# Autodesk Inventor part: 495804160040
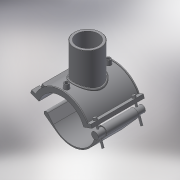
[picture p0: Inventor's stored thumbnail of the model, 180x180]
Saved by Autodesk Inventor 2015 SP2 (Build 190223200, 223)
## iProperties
Created: 2017-07
Part Number: 495804160040
Material: Generic
Description: PLASSON BRANCH SADDLE 160-40
Document SubType Name: Modeling
Designer: KIM
Density: 1 g/cm^3
Appearance: Default
Author: KIM
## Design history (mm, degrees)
derived "495804.ipt"
feature "Solid1::495804.ipt"
feature "Solid2::495804.ipt"
tag "TaggingFeature1"
body "Solid1"
body "Solid2"
other parameters: "d4" = 118, "d5" = 0, "d6" = 0.1, "d8" = 0, "d19" = 6, "d20" = 6, "d21" = 70.8, "d23" = 0, "d24" = 35.4, "d26" = 0, "d27" = 3, "d28" = 3, "d29" = 3, "d30" = 53.33333, "d31" = 6, "d32" = 0, "d33" = 0, "d34" = 0.6, "d40" = 93.6, "d41" = 44, "d43" = 0, "d45" = 0, "d47" = 168, "d50" = 0, "d70" = 15, "d72" = 0, "d73" = 6, "d75" = 5, "d76" = 0, "d77" = 8, "d79" = 15, "d80" = 47.2, "d82" = 5 deg, "d84" = 4, "d85" = 14, "d86" = 0, "d87" = 3, "d88" = 0, "d89" = 1, "d90" = 1, "d91" = 94.4, "d92" = 0, "d93" = 0.5, "d94" = 84.21053, "d96" = 183.6, "d97" = 2.36, "d98" = 0, "d102" = 1.2, "d103" = 32, "d105" = 0, "d109" = -26, "d117" = 0.4, "d120" = 140 deg, "d121" = 24.228, "d122" = 20 deg, "d124" = 108, "d126" = 0, "d143" = 168, "d150" = 28.8, "d159" = 4, "d161" = 4, "d162" = 70.8, "d163" = 0, "d167" = 32, "d168" = 81.81818, "d173" = 1, "d176" = 20 deg, "d177" = 11.2, "d180" = 0, "d185" = 38.35, "d186" = 38.35, "d188" = 6, "d189" = 11.2, "d190" = 0, "d191" = 135, "d202" = 0, "d216" = 106.2, "d217" = 0, "d221" = 43.66, "d222" = 11.2, "d223" = 6.72, "d225" = 6.72, "d227" = 23.04, "d230" = 99.2, "d236" = 20 deg, "d237" = 97, "d238" = 20 deg, "d239" = 11.2, "H_" = 78, "L_" = 118, "d_t" = 6, "H_1" = 68, "d148" = 4, "d160" = 4
